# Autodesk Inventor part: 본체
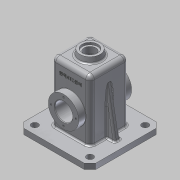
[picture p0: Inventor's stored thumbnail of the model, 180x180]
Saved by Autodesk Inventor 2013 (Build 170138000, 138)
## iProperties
Created: 2016-02
Part Number: 본체
Material: 알루미늄 6061
Document SubType Name: Modeling
Designer: dgall
Density: 2.71 g/cm^3
Mass: 931.159 g
Surface Area: 1047.57 cm^2
Volume: 343.601 cm^3
Author: dgall
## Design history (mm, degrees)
sketch "스케치1"
  geometry: L1 (-35, 65)-(35, 65); L2 (35, 65)-(35, -55); L3 (35, -55)-(-35, -55); L4 (-35, -55)-(-35, 65); 1 further point
  constraints: 8 end point, 2 parallel, 1 horizontal, 1 perpendicular
  dimensions: "d0" = 70 distance of L1.start L1.end; "d3" = 35 distance from line of point (0, 0) L4 (= 0.5 x d0); "d5" = 120 distance of L1.end L2.end; "d6" = 55 distance from line of L3 point (0, 0)
extrude "돌출1" new body sketch "스케치1" stored distance "d7" = 70; taper "d8" = 0 deg
feature "쉘1" dims "d9" = 5
sketch "스케치2"
  geometry: L1 (0, 68.106)-(0, 38.78); L2 (0, 75)-(18.237, 75); L3 (18.237, 75)-(20, 65); L4 (35, 65)-(-35, 65) reference; L5 (35, -55)-(35, 65) reference; L6 (0, 75)-(0, 65); L7 (20, 65)-(0, 65); 1 further point
  constraints: 10 end point, 2 point on line, 1 collinear, 1 midpoint, 1 perpendicular, 1 vertical, 1 vertical alignment
  dimensions: "d10" = 40 diameter of L3.end L1; "d12" = 10 distance between parallel lines of L4 L2; "d13" = 10 deg angle of L5 L3
revolve "회전1" sketch "스케치2" stored, may be unused: angle "d14" = 90 deg
sketch "스케치3"
  geometry: C1 r 18.237 at (0, 0) reference; C2 r 10.5 at (0, 0)
  constraints: 1 centre point, 1 coincident
  dimensions: "d15" = 21 diameter of C2
extrude "돌출2" cut sketch "스케치3" distance "d18" = 70; taper "d19" = 0 deg
sketch "스케치4"
  geometry: C1 r 10.5 at (0, 0) reference; C2 r 18.237 at (0, 0) reference; C3 r 14 at (0, 0)
  constraints: 1 centre point, 1 coincident
  dimensions: "d20" = 28 diameter of C3
extrude "돌출3" cut sketch "스케치4" distance "d22" = 4; taper "d23" = 0 deg
sketch "스케치5"
  geometry: L1 (70, 0)-(0, 0) reference; C1 r 16 at (35, 55); 1 further point
  constraints: 1 centre point, 1 coincident
  dimensions: "d24" = 32 diameter of C1; "d26" = 55 distance from line of L1 C1.centre (derived)
extrude "돌출4" cut sketch "스케치5" stored distance "d27" = 4; taper "d28" = 0 deg
sketch "스케치6"
  geometry: L1 (-35, 16)-(-30, 16) reference; L2 (-35, -55)-(-35, 65) reference; L3 (-30, -55)-(-30, 60) reference; L4 (-35, 27.5)-(-48, 27.5); L5 (-48, 27.5)-(-48, 16); L6 (-48, 16)-(-23, 16); L7 (-23, 16)-(-23, 20.5); L8 (-23, 20.5)-(-30, 27.5); L9 (-30, 27.5)-(-30, 16); L10 (-35, 27.5)-(-35, 16); L11 (0, 0)-(-45.049, 0); L12 (-35, 27.5)-(-30, 27.5); L13 (-35, 27.5)-(-30, 27.5)
  constraints: 20 end point, 5 perpendicular, 3 collinear, 3 point on line, 1 parallel
  dimensions: "d29" = 55 diameter of L4 L11; "d31" = 7 distance between parallel lines of L7 L3; "d32" = 13 distance between parallel lines of L2 L5; "d33" = 135 deg angle of L8 L3
revolve "회전2" sketch "스케치6" stored, may be unused: angle "d34" = 90 deg
sketch "스케치7" dims "d35" = 45
  geometry: C1 r 27.5 at (0, 0) reference; C2 r 16 at (0, 0) reference; C3 r 2 at (0, 22.5); 1 further point
  constraints: 2 vertical alignment, 1 centre point, 1 coincident, 2 other
  dimensions: "d37" = 4 diameter of C3
hole "구멍1" sketch "스케치7" at (0, 22.5) diameter "d38" = 3.242; stored, may be unused: countersink angle "d42" = 90 deg, drill point angle "d44" = 118 deg; dims "d39" = 8, "d40" = 4, "d41" = 2, "d43" = 10
sketch "스케치8"
  geometry: L1 (0, 0)-(70, 0) reference; L2 (0, -70)-(0, 0) reference; L3 (0, -70)-(70, -70) reference; L4 (70, 0)-(70, -70) reference; L5 (-30, 30)-(100, 30); L6 (100, 30)-(100, -100); L7 (100, -100)-(-30, -100); L8 (-30, -100)-(-30, 30); 1 further point
  constraints: 8 end point, 2 parallel, 1 horizontal, 1 perpendicular
  dimensions: "d48" = 130 distance of L5.start L5.end; "d50" = 130 distance between parallel lines of L7 L5; "d51" = 65 distance from line of point (35, -35) L5 (= 0.5 x d50); "d52" = 65 distance from line of point (35, -35) L8 (= 0.5 x d48)
extrude "돌출5" join sketch "스케치8" distance "d53" = 10; taper "d54" = 0 deg
chamfer "모따기1" distance "d55" = 10; stored, may be unused: second distance "d56" = 2, angle "d57" = 45 deg
sketch "스케치9"
  geometry: L1 (0, 0)-(110, 0) reference; L2 (-10, -120)-(-10, -10) reference; C1 r 6 at (5, -15); 1 further point
  constraints: 1 centre point
  dimensions: "d58" = 15 distance from line of C1.centre L1; "d59" = 15 distance from line of C1.centre L2; "d60" = 12 diameter of C1
extrude "돌출6" cut sketch "스케치9" distance "d61" = 10; taper "d62" = 0 deg
fillet "모깎기1" dims "d63" = 8
fillet "모깎기2" dims "d64" = 8
fillet "모깎기4" dims "d66" = 3
chamfer "모따기2" distance "d67" = 1; stored, may be unused: second distance "d68" = 2, angle "d69" = 45 deg
fillet "모깎기5" dims "d70" = 0.5
fillet "모깎기6" dims "d71" = 0.5
sketch "스케치10"
  geometry: L1 (7.59, -4.264)-(46.41, -4.264); L2 (46.41, -4.264)-(46.41, -19.736); L3 (46.41, -19.736)-(7.59, -19.736); L4 (7.59, -19.736)-(7.59, -4.264); L5 (7.59, -12)-(46.41, -12); L6 (27, -4.264)-(27, -19.736); L7 (8.763, 18)-(45.237, 18) reference; L8 (62, -102)-(62, 0) reference; 1 further point
  constraints: 4 end point, 4 midpoint, 2 other
  dimensions: "d72" = 30 distance between parallel lines of L5 L7; "d73" = 35 distance between parallel lines of L6 L8
extrude "돌출7" join sketch "스케치10" distance "d74" = 0.5; taper "d75" = 0 deg
sketch "스케치11"
  geometry: L1 (-35, 40.069)-(-50, -45); L2 (55, -45)-(-55, -45) reference; L3 (-35, -45)-(-35, 57) reference; L4 (-65, -45)-(-55, -45) reference; L5 (-55, -45)-(-55, -55) reference; L6 (-55, -55)-(-65, -55) reference; L7 (-65, -55)-(-65, -45) reference; L8 (44, -45)-(56, -45) reference; L9 (56, -55)-(44, -55) reference; L10 (55, -45)-(65, -45) reference; L11 (65, -45)-(65, -55) reference; L12 (65, -55)-(55, -55) reference; L13 (55, -55)-(55, -45) reference; L14 (35, 57)-(35, -45) reference; L15 (50, -45)-(35, 40.069); 3 further points
  constraints: 4 end point, 3 point on line, 1 midpoint
  dimensions: "d76" = 15 distance from line of L1.end L7; "d77" = 10 deg angle of L1 L7; "d78" = 15 distance from line of L15.start L11; "d79" = 10 deg angle of L15 L11
  node "투영된 루프1"
  node "투영된 루프2"
  node "투영된 루프3"
feature "리브1" dims "d80" = 1, "d81" = 10, "d82" = 0, "d83" = 0, "d84" = 1, "d85" = 1
feature "리브2" dims "d86" = 1, "d87" = 10, "d88" = 0, "d89" = 0, "d90" = 1, "d91" = 1
fillet "모깎기7" dims "d92" = 3
fillet "모깎기8" dims "d93" = 3
fillet "모깎기9" dims "d94" = 3
fillet "모깎기10" dims "d95" = 3
fillet "모깎기11" dims "d96" = 3
fillet "모깎기12" dims "d97" = 3
node "솔리드1"
pattern_circular "원형 패턴1" dims angle "d46" = 360 deg
mirror "대칭1"
mirror "대칭2"
mirror "대칭3"
